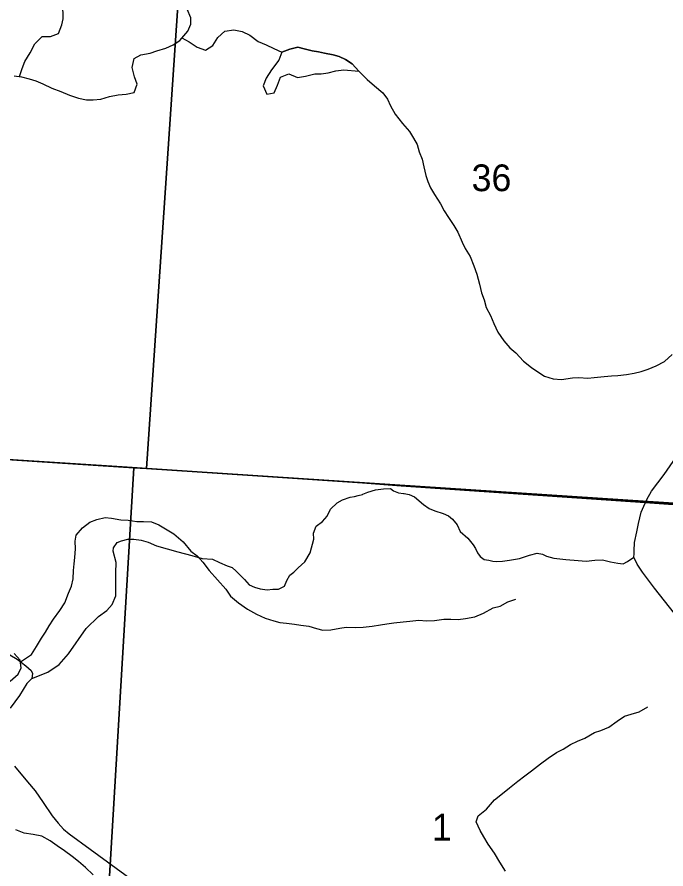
# Model space of a CAD drawing. Extents: x 0 to 34, y 0 to 22.
# Drawn here: x 4.198 to 5.215, y 18.42 to 19.753 of the extents above; entities that cross this region are included whole.
import ezdxf

# ---------------------------------------------------------------- set-up
doc = ezdxf.new("R2010")
doc.units = 0
for name, color, linetype in [('GM_X_Major_River', 7, 'Continuous'), ('GM_X_Minor_Lake', 7, 'Continuous'), ('GM_X_Minor_River', 7, 'Continuous'), ('GM_X_Section', 7, 'Continuous'), ('GM_X_Section_Text', 7, 'Continuous'), ('GM_X_Township_Road', 7, 'Continuous'), ('SC_Scratch1', 7, 'Continuous')]:
    doc.layers.add(name, color=color, linetype=linetype)

msp = doc.modelspace()

# ---------------------------------------------------------------- linework, layer by layer
at = {"layer": 'GM_X_Major_River'}
for points in [[(4.1933, 19.6614), (4.205, 19.6598), (4.2168, 19.6567), (4.2274, 19.6536), (4.2384, 19.649), (4.2523, 19.642), (4.2663, 19.637), (4.2803, 19.6312), (4.2943, 19.6262), (4.3065, 19.6238), (4.3171, 19.6237), (4.3292, 19.6248), (4.3429, 19.6289), (4.3562, 19.6314), (4.3691, 19.6328), (4.3813, 19.6354), (4.3863, 19.6483), (4.3822, 19.66), (4.3785, 19.6745), (4.3816, 19.6885), (4.3919, 19.6941), (4.4063, 19.697), (4.417, 19.7004), (4.431, 19.7048), (4.4424, 19.7097), (4.4531, 19.7168), (4.4657, 19.7311), (4.4704, 19.7421), (4.4704, 19.7523), (4.4644, 19.7657)], [(4.187, 18.7139), (4.1996, 18.7248), (4.2042, 18.7346), (4.2028, 18.7464), (4.1934, 18.7571)], [(4.317, 18.4106), (4.305, 18.422), (4.294, 18.4316), (4.2842, 18.4393), (4.2721, 18.4481), (4.2608, 18.4561), (4.2498, 18.4638), (4.2366, 18.4711), (4.223, 18.4738), (4.2093, 18.4755), (4.1961, 18.4809)]]:
    msp.add_lwpolyline(points, dxfattribs=at)
at = {"layer": 'GM_X_Minor_Lake'}
for points in [[(4.7333, 19.6687), (4.723, 19.6804), (4.7124, 19.6868), (4.7025, 19.6917), (4.6931, 19.6944), (4.6798, 19.6966), (4.6703, 19.6989), (4.6605, 19.7007), (4.6476, 19.7037), (4.6378, 19.7064), (4.6253, 19.7033), (4.6128, 19.6984)], [(4.6128, 19.6984), (4.6083, 19.6858), (4.5966, 19.6706), (4.5883, 19.6577), (4.5838, 19.6456), (4.5895, 19.6327), (4.6009, 19.6346), (4.6058, 19.6468), (4.6107, 19.6593), (4.6239, 19.6643), (4.6375, 19.6586), (4.65, 19.6609), (4.6648, 19.6647), (4.6746, 19.6644), (4.6852, 19.6663), (4.6973, 19.6694), (4.7102, 19.6709), (4.7333, 19.6687)]]:
    msp.add_lwpolyline(points, dxfattribs=at)
at = {"layer": 'GM_X_Minor_River'}
for points in [[(4.202, 19.6603), (4.206, 19.6727), (4.2101, 19.6837), (4.2184, 19.6974), (4.2259, 19.7114), (4.2372, 19.7232), (4.2505, 19.7232), (4.2629, 19.7278), (4.2682, 19.7411), (4.2701, 19.7506), (4.27, 19.7601), (4.2688, 19.7745), (4.2654, 19.7881), (4.2551, 19.801), (4.2419, 19.81), (4.229, 19.8187), (4.2179, 19.8304), (4.213, 19.8426)], [(4.4564, 19.7206), (4.4678, 19.7147), (4.4803, 19.7064), (4.4932, 19.7018), (4.5049, 19.7091), (4.5124, 19.7216), (4.5237, 19.7315), (4.5377, 19.7334), (4.5506, 19.7308), (4.5628, 19.7248), (4.5757, 19.7153), (4.5882, 19.7097), (4.6003, 19.704), (4.6128, 19.6984), (4.6253, 19.7033), (4.6378, 19.7064), (4.6476, 19.7037), (4.6605, 19.7007), (4.6703, 19.6989), (4.6798, 19.6966), (4.6931, 19.6944), (4.7025, 19.6917), (4.7124, 19.6868), (4.723, 19.6804), (4.7333, 19.6687), (4.7466, 19.6555), (4.7583, 19.6456), (4.7712, 19.6347), (4.7785, 19.6248), (4.783, 19.6146), (4.7907, 19.6014), (4.8021, 19.5866), (4.8131, 19.5741), (4.8192, 19.5639), (4.8249, 19.5537), (4.8283, 19.5423), (4.8325, 19.531), (4.8356, 19.5188), (4.8383, 19.5056), (4.8417, 19.4961), (4.8459, 19.4859), (4.852, 19.4756), (4.8615, 19.4609), (4.8672, 19.4499), (4.8741, 19.4397), (4.8824, 19.4272), (4.8885, 19.4166), (4.8954, 19.4011), (4.9, 19.3908), (4.908, 19.3784), (4.9137, 19.364), (4.9186, 19.3511), (4.9225, 19.3352), (4.9259, 19.3215), (4.9298, 19.3109), (4.9328, 19.2988), (4.9397, 19.2863), (4.945, 19.2734), (4.9515, 19.2602), (4.9606, 19.2466), (4.9701, 19.2356), (4.9796, 19.2276), (4.9914, 19.2148), (5.0039, 19.205), (5.0138, 19.1982), (5.0244, 19.1914), (5.038, 19.1869), (5.0509, 19.1861), (5.0683, 19.1888), (5.0785, 19.1892), (5.0925, 19.1881), (5.1024, 19.1889), (5.1179, 19.1905), (5.1292, 19.1916), (5.1395, 19.1924), (5.1527, 19.1936), (5.1648, 19.1959), (5.1758, 19.1986), (5.1871, 19.2024), (5.1996, 19.2073), (5.2125, 19.2142), (5.2245, 19.2252)], [(4.2031, 18.7441), (4.2206, 18.7553), (4.2286, 18.7678), (4.2365, 18.7811), (4.2425, 18.7906), (4.2485, 18.8005), (4.2549, 18.8107), (4.2651, 18.8244), (4.2726, 18.8362), (4.2786, 18.8517), (4.2835, 18.8623), (4.2858, 18.8737), (4.2865, 18.887), (4.2876, 18.8976), (4.2883, 18.9075), (4.2894, 18.9207), (4.289, 18.9329), (4.2904, 18.9424), (4.3003, 18.9538), (4.312, 18.9625), (4.3229, 18.9667), (4.3362, 18.9698), (4.346, 18.9687), (4.3604, 18.9664), (4.3721, 18.9657), (4.3858, 18.9638), (4.396, 18.9639), (4.4085, 18.9631), (4.4202, 18.9586), (4.4305, 18.9522), (4.4438, 18.9443), (4.4582, 18.9318), (4.4703, 18.9174), (4.4802, 18.9098), (4.4889, 18.9), (4.4992, 18.8871), (4.525, 18.8576), (4.5326, 18.8467), (4.5452, 18.8365), (4.5588, 18.8266), (4.5729, 18.8187), (4.5869, 18.8123), (4.6001, 18.8082), (4.6096, 18.8055), (4.6202, 18.8044), (4.6327, 18.8029), (4.6426, 18.8014), (4.6551, 18.7999), (4.6672, 18.7962), (4.677, 18.7936), (4.6895, 18.794), (4.7035, 18.7967), (4.7137, 18.7982), (4.7285, 18.7975), (4.7402, 18.7983), (4.7542, 18.7998), (4.7675, 18.8017), (4.7773, 18.8033), (4.7883, 18.8052), (4.8031, 18.8068), (4.8133, 18.8079), (4.8276, 18.8091), (4.8394, 18.8084), (4.8519, 18.8088), (4.8666, 18.8107), (4.8776, 18.8107), (4.8893, 18.8104), (4.9007, 18.8116), (4.9151, 18.8142), (4.9291, 18.8203), (4.9438, 18.8287), (4.9548, 18.831), (4.9672, 18.8379), (4.9793, 18.8421)], [(4.9542, 18.4306), (4.9462, 18.4443), (4.9363, 18.4587), (4.9294, 18.47), (4.9234, 18.4799), (4.9172, 18.4935), (4.9206, 18.503), (4.9338, 18.5132), (4.9463, 18.5277), (4.9561, 18.536), (4.9697, 18.5467), (4.9825, 18.5573), (4.9935, 18.5653), (5.0041, 18.5733), (5.0184, 18.5844), (5.0301, 18.5931), (5.0433, 18.6019), (5.0539, 18.6072), (5.0652, 18.6148), (5.0762, 18.6198), (5.0875, 18.6247), (5.1027, 18.6335), (5.1125, 18.6365), (5.1253, 18.6419), (5.1382, 18.651), (5.1499, 18.659), (5.1601, 18.6621), (5.173, 18.6655), (5.1862, 18.6735)], [(4.9633, 18.4163), (4.9542, 18.4306)]]:
    msp.add_lwpolyline(points, dxfattribs=at)
at = {"layer": 'GM_X_Section'}
for points in [[(4.4687, 20.0485), (4.4009, 19.0464), (4.3808, 19.0475), (3.4007, 19.112), (3.4572, 20.1141)], [(4.4687, 20.0485), (5.483, 19.983), (5.4174, 18.9797), (4.4009, 19.0464)], [(3.378, 19.1131), (3.4007, 19.112), (4.3808, 19.0475), (4.3187, 18.0057), (3.3075, 18.0826)], [(4.3808, 19.0475), (4.4009, 19.0464), (5.4174, 18.9797), (5.3412, 17.9492), (4.3187, 18.0057)]]:
    msp.add_lwpolyline(points, close=True, dxfattribs=at)
at = {"layer": 'GM_X_Township_Road'}
for points in [[(5.1645, 18.9079), (5.1651, 18.9133), (5.1651, 18.9175), (5.1653, 18.9308), (5.1693, 18.9475), (5.172, 18.9606), (5.1761, 18.9784), (5.1822, 18.9926), (5.1846, 18.9981), (5.192, 19.0112), (5.212, 19.037), (5.2403, 19.0778)], [(4.2212, 18.7177), (4.2461, 18.7279), (4.2638, 18.7398), (4.2783, 18.7564), (4.3061, 18.796), (4.3254, 18.8148), (4.3388, 18.8243), (4.347, 18.8337), (4.3526, 18.8472), (4.3526, 18.8835), (4.353, 18.8993), (4.3487, 18.9172), (4.3491, 18.9227), (4.3546, 18.9308), (4.3618, 18.9333), (4.3717, 18.9358), (4.3809, 18.9358), (4.3924, 18.9347), (4.4032, 18.9315), (4.4167, 18.9257), (4.4499, 18.916), (4.4717, 18.9105), (4.4878, 18.9059), (4.5042, 18.9048), (4.5154, 18.8997), (4.5272, 18.8942), (4.5348, 18.8919), (4.5414, 18.8859), (4.5476, 18.8799), (4.5543, 18.8728), (4.5614, 18.8643), (4.5699, 18.8611), (4.5789, 18.8581), (4.5897, 18.8567), (4.5985, 18.8578), (4.6074, 18.8576), (4.6169, 18.8624), (4.6206, 18.8714), (4.6254, 18.8795), (4.6316, 18.8841), (4.6385, 18.8912), (4.6489, 18.9006), (4.6572, 18.9146), (4.6631, 18.9361), (4.6627, 18.9453), (4.6664, 18.9563), (4.6766, 18.9639), (4.684, 18.9722), (4.6889, 18.983), (4.6997, 18.9931), (4.7077, 18.9977), (4.7199, 19.0018), (4.7266, 19.003), (4.7324, 19.0044), (4.739, 19.0062)], [(4.739, 19.0062), (4.74, 19.0065), (4.7478, 19.0097), (4.7595, 19.0131), (4.7724, 19.0147), (4.783, 19.0154), (4.788, 19.0115), (4.7956, 19.0085), (4.8037, 19.0076), (4.8046, 19.0074)], [(4.8046, 19.0074), (4.8126, 19.0058), (4.8209, 19.0023), (4.8347, 18.9901), (4.8439, 18.9839), (4.8527, 18.9805), (4.8656, 18.9763), (4.8738, 18.9724), (4.8803, 18.9671), (4.8874, 18.9584), (4.8925, 18.9482), (4.9042, 18.9377), (4.9129, 18.9269), (4.9164, 18.9213), (4.9196, 18.9147), (4.9238, 18.9091), (4.93, 18.9043), (4.9371, 18.9029), (4.9435, 18.9018), (4.9495, 18.9013), (4.9587, 18.9016), (4.9695, 18.9029), (4.9854, 18.9055), (5.0008, 18.9112), (5.0132, 18.914), (5.0211, 18.9124), (5.0277, 18.9094), (5.0392, 18.9061), (5.0579, 18.9043), (5.0774, 18.9025), (5.0896, 18.9016), (5.1034, 18.9032), (5.1154, 18.9036), (5.1278, 18.9006), (5.1393, 18.8983), (5.1478, 18.8972), (5.1547, 18.9013), (5.1645, 18.9079)], [(5.2439, 18.7997), (5.1968, 18.8592), (5.178, 18.8844), (5.1696, 18.8971), (5.1645, 18.9079)], [(4.178, 18.7601), (4.198, 18.7481), (4.2118, 18.7375), (4.2201, 18.7304), (4.2221, 18.7256), (4.2212, 18.7177), (4.2132, 18.7099), (4.2017, 18.6915), (4.1869, 18.6713)], [(4.1938, 18.5809), (4.2143, 18.556), (4.2263, 18.542), (4.2387, 18.524), (4.2527, 18.5027), (4.2626, 18.4912), (4.2709, 18.482), (4.2796, 18.4748), (4.3123, 18.4507), (4.4078, 18.3814)]]:
    msp.add_lwpolyline(points, dxfattribs=at)
at = {"layer": 'SC_Scratch1'}
for points in [[(5.53, 20.9), (2.1, 20.9), (2.1, 19.1982), (2.3572, 19.1804), (3.3448, 19.1146), (4.3628, 19.0495), (4.7394, 19.0241), (4.7997, 19.0196), (5.182, 18.9932), (5.4007, 18.9779), (5.4089, 19.0989), (5.4469, 19.6641), (5.4955, 20.3864)], [(2.1, 19.1982), (2.1, 14.1), (5.0535, 14.1), (5.0814, 14.5016), (5.1049, 14.8414), (5.1794, 15.9156), (5.2761, 17.2534), (5.2869, 17.4026), (5.3506, 18.2846), (5.3662, 18.4999), (5.4007, 18.9779), (5.182, 18.9932), (4.7997, 19.0196), (4.7394, 19.0241), (4.3628, 19.0495), (3.3448, 19.1146), (2.3572, 19.1804)]]:
    msp.add_lwpolyline(points, close=True, dxfattribs=at)

# ---------------------------------------------------------------- texts
at = {"layer": 'GM_X_Section_Text'}
for s, height, p in [('36', 0.04186, (4.9102, 19.4808)), ('1', 0.0419, (4.8481, 18.4642))]:
    msp.add_text(s, height=height, rotation=0, dxfattribs=at).set_placement(p)

doc.saveas('drawing.dxf')
